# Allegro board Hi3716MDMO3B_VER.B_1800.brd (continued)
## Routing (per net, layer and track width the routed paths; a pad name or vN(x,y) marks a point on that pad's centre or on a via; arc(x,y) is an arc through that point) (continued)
$13N54: length 4
  TOP w0.127: Q8.1 208.82,107.71 209.33,108.21 R126.2 R125.1
$13N57: length 5.1
  TOP w0.127: R125.2 211.24,110.78 J17.2
$14N137: length 1.4
  TOP w0.127: R69.1 D17.1
$15N244: length 2.8
  TOP w0.254: U17.6 229.02,125.24 229.39,125.62 R251.2
$15N245: length 2.8
  TOP w0.254: R250.2 227.36,125.62 227.75,125.23 U17.7
$15N246: length 3.1
  TOP w0.254: R252.2 226.48,125.31 U17.8
$15N325: length 4.5
  TOP w0.254: U12.4 224.21,123.18 223.29,124.1 R65.2
$16N143: length 2
  TOP w0.127: U9.11 208.09,127.26 R5.1
$16N153: length 19.8
  TOP w0.254: R89.1 212.95,123.07 C60.1 211.78,125.96 211.13,126.61 U9.12 208.93,126.61 208.32,125.99 206.16,125.99 204.43,127.72 R113.1 R175.1
$16N171: length 2.1
  TOP w0.127: R49.2 206.67,128.3 206.73,128.24 R190.1 207.17,127.77 207.27,127.67 R5.2
$16N236: length 2
  TOP w0.127: C27.2 215.95,128.56 U9.6
$16N249: length 27.5
  TOP w0.254: R90.2 215.41,122.94 C57.2 215.4,123.48 214.67,124.22 214.67,126.17 215.11,126.61 U9.3 218.59,126.61 219.24,127.26 219.24,129.42 218.35,130.31 216.06,130.31 214.36,132.01 208.01,132.01 207.06,132.96 R112.1 R174.2
$16N268: length 5.1
  TOP w0.254: R92.1 218.96,122.72 219.54,122.13 R88.2 C180.1 216.61,121.55 R90.1
$16N273: length 5.5
  TOP w0.254: C57.1 R92.2 217.49,125.33 216.86,125.96 U9.2
$16N280: length 1.5
  TOP w0.254: R88.1 220.36,120.07 C234.2
$16N296: length 12.6
  TOP w0.127: C38.1 R50.2 208.55,122.19 R185.1 208.55,123.72 v1(208.32,123.96) ; U9.5 v1(214.67,127.91)
  BOTTOM w0.127: v1(208.32,123.96) 212.27,127.91 v1(214.67,127.91)
$16N316: length 3.9
  TOP w0.127: U9.7 213.76,129.21 213.29,129.68 C28.1
$16N318: length 3.6
  TOP w0.127: C28.2 212.48,129.65 212.04,129.21 U9.8
$16N327: length 6.7
  TOP w0.254: U9.13 209.17,125.96 208.82,125.61 208.82,124.85 209.59,124.09 210.48,124.09 210.97,123.6 C60.2 210.97,121.83 R109.1
$16N332: length 3.9
  TOP w0.254: R87.1 R109.2 C181.1 R89.2
$16N368: length 2.1
  TOP w0.254: C235.1 211.01,118.79 211.01,119.77 R87.2
$16N387: length 7.2
  TOP w0.508: U11.2 182.53,141.37 183.64,140.25 C102.1 LB17.2
$17N94: length 5.2
  TOP w0.165: U22.13 249.04,136.36 248.83,136.15 248.83,133.49 248.2,132.86 248.2,132.63 R30.1
$17N123: length 4.4
  TOP w0.508: U13.1 244.59,110.21 244.73,110.35 R8.1 244.86,112.53 R192.1
$17N126: length 3.5
  TOP w0.381: C182.1 243.85,104.38
  TOP w0.635: 240.45,107.05 C39.1 237.91,107.05
$17N128: length 7.8
  TOP w0.381: R192.2 251.62,112.53 253.91,110.25
$17N139: length 3.2
  TOP w0.165: R30.2 248.23,131.03 248.23,130.7 R63.2 248.32,129.67 248.32,129.19 C52.1
$17N140: length 3.3
  TOP w0.165: C55.1 247.81,129.24 247.81,129.64 R63.1 247.94,130.76 247.94,130.96 R31.2
$17N221: length 7.2
  TOP w0.127: R28.1 C50.1 250.89,130.69 249.97,131.61 249.97,135.53 250.09,135.65 U22.14
$17N517: length 2.9
  TOP w0.152: U22.17 251.59,135.93 253.13,134.39 C47.1
$17N528: length 1.3
  TOP w0.152: C1.1 R29.2
$17N535: length 3.2
  TOP w0.152: R29.1 251.05,133.78 C135.1 250.59,135.07 U22.15
$17N549: length 5.5
  TOP w0.165: R31.1 247.91,132.63 247.91,132.98 248.54,133.61 248.54,136.27 248.84,136.58 U22.12
$17N569: length 12.7
  TOP w0.203: U22.8 247.6,139.11 247.05,138.57 247.05,135.9 246.92,135.78 C262.1 246.13,135.57 243.79,135.57 243.23,136.13 243.23,139.97 X2.1
$17N571: length 12.4
  TOP w0.203: X2.2 243.24,133.71 244.22,134.69 C263.1 246.35,134.69 247.43,135.77 247.43,138.06 247.99,138.61 U22.9
$17N582: length 30.7
  TOP w0.127: R35.2 241.11,124.62 R43.1 C33.1 240.96,126.78 240.96,127.77 240.17,128.56 240.17,142.27 241.64,143.75 244.79,143.75 245.78,142.76 245.78,140.98 246.4,140.36 U22.6
$17N583: length 29.9
  TOP w0.127: U22.7 248.84,139.62 246.59,139.62 245.4,140.81 245.4,142.63 244.61,143.42 241.74,143.42 240.45,142.12 240.45,128.79 241.34,127.9 241.34,127.36 C34.1 R41.1 R37.2
$17N610: length 2.8
  TOP w0.152: C61.2 248.14,141.57 249.38,141.57 250.09,140.86 U22.5
$17N615: length 3.7
  TOP w0.152: C143.2 248.68,142 249.44,142 250.59,140.84 U22.4
$17N624: length 3.6
  TOP w0.44: C187.2 248.92,145.17 249.95,144.13 ; C188.1 249.95,144.13 ; 249.95,144.13 D15.3
$17N628: length 1.8
  TOP w0.254: U22.3 251.09,141.36
  TOP w0.44: 251.09,141.36 C188.2
$17N631: length 1.6
  TOP w0.44: C187.1 247.4,146.67 R27.2
$17N637: length 2.8
  TOP w0.152: L3.1 254.67,135.78 253.33,137.11 U22.19
$17N639: length 2.6
  TOP w0.152: L3.2 254.28,137.3 253.47,138.11 U22.21
$17N641: length 4.7
  TOP w0.152: U22.20 253.34,137.61 254.37,136.58 256.04,136.58 L1.1
$17N643: length 4.5
  TOP w0.152: U22.22 252.84,138.61 253.48,138.61 254.04,138.06 255.69,138.06 256.39,137.35 L1.2
$17N657: length 2
  TOP w0.254: U22.24 253.05,139.61 253.15,139.71
  TOP w0.44: 253.15,139.71 253.66,139.71 253.78,139.84 arc(254.05,140.24) L5.2
$17N674: length 1
  TOP w0.44: C48.2 L5.1
$17N676: length 2.2
  TOP w0.44: C190.1 C185.2 257.66,141.11 arc(257.24,140.83) C48.1
$17N678: length 3.8
  TOP w0.44: C189.1 258.53,143.49 arc(259.11,143.37) C184.1 ; C184.1 L12.2 ; C184.1 C206.2
$17N683: length 1.3
  TOP w0.44: 260.12,139.98 L9.2
$17N685: length 1
  TOP w0.44: L10.2 255.71,143.24 C190.2
$17N699: length 4.4
  TOP w0.254: R64.1 255.99,139.51 254.98,139.51 254.65,139.18 C134.2 254.48,139.11 U22.23
$17N726: length 2.1
  TOP w0.44: 259.13,140.97 259.13,140.97 C185.1 C184.2
$17N732: length 1
  TOP w0.44: C189.2 L11.2
$17N744: length 4.6
  TOP w0.254: U22.18 252.09,136.07 252.89,135.26 253,135.26 C41.2 255.55,134.1 R84.1
$17N767: length 1.7
  TOP w0.44: L12.1 262.18,143.04 arc(262.72,142.94) D13.3
$18N11: length 2.6
  TOP w0.127: R32.2 R231.2 261.53,76.58 Q11.2
$18N28: length 7.5
  TOP w0.127: U23.13 248.57,71.63 248.19,71.26 R236.1 246.31,72.5 246.03,72.79 U23.11
$18N32: length 54.1
  TOP w0.127: U23.9 243.49,72.77 243.11,72.4 226.35,72.4 221.04,67.09 208.11,67.09 R36.2
$18N33: length 6.4
  TOP w0.127: R222.2 R9.2 261.76,90.2 262.16,89.8 262.16,88.27 261.91,88.02 260.51,88.02 260.26,87.77 Q2.1
$18N35: length 5.5
  TOP w0.381: R9.1 262.57,87.16 Q2.2
  TOP w0.508: LB20.2 Q2.2
$18N36: length 1.5
  TOP w0.508: R274.1 260.28,89.16 Q2.3
$18N96: length 8
  TOP w0.127: J1.6 254.28,69.5 C307.1 R129.2 R128.1 R106.2
$19N8: length 18.8
  TOP w0.381: R136.1 27.47,73.92 27.98,73.42 30.26,73.42 31.02,74.18 31.02,84.46 30.64,84.85 29.63,84.85 28.97,85.51 C198.1 28.23,85.73
$19N10: length 20
  TOP w0.381: 28.87,107.83 C199.1 29.48,107.48 30.14,106.82 30.14,100.09 29.12,99.07 29.12,95.77 28.74,95.39 28.11,95.39 27.43,96.07 R137.1
  TOP w0.635: C236.1 28.95,115.5 ; C236.1 27.87,114.23 ; C236.1 28.95,112.96
$19N25: length 2.3
  TOP w0.254: D12.2 11.24,103.36 R241.1
$19N26: length 2
  TOP w0.254: R241.2 12.7,101.09 Q9.3
$19N27: length 1.8
  TOP w0.381: Q9.2 R4.1
$19N28: length 1.8
  TOP w0.381: Q9.1 R38.2
$19N31: length 1.5
  TOP w0.254: Q10.1 10.03,80.45 R39.2
$19N32: length 1.9
  TOP w0.381: Q10.2 R3.1
$19N33: length 2.4
  TOP w0.254: R240.2 12.2,83.89 Q10.3
$19N34: length 2.3
  TOP w0.254: D11.2 10.73,87.11 R240.1
$19N40: length 3.2
  TOP w0.508: S2.1 R242.2
$19N44: length 3.4
  TOP w0.381: C63.1 26.29,75.52 C252.1 26.19,76.48 26.03,76.63 U6.6
$19N56: length 2.3
  TOP w0.381: C197.1 28.57,75.76 U6.8
$19N57: length 2.3
  TOP w0.381: R136.2 27.47,76.46 27.3,76.63 U6.7
$19N58: length 1.7
  TOP w0.381: C228.1 30.08,83.18 U6.1
$19N59: length 1
  TOP w0.381: C252.2 25.4,75.6 R238.1
$19N60: length 3.8
  TOP w0.381: R1.1 23.19,75.65 R83.1 24.38,76.17 24.76,76.55 U6.5
$19N61: length 4.5
  TOP w0.381: v1(28.48,84.72) 28.99,84.72 29.58,84.13 C228.2
  BOTTOM w0.381: v1(28.48,84.72) v1(25.94,84.72)
$19N64: length 5
  TOP w0.381: C229.2 29.5,106.56 v1(29.12,106.94)
  BOTTOM w0.381: v1(29.12,106.94) v1(25.18,106.94)
$19N65: length 3.4
  TOP w0.381: R10.1 R82.1 23.62,98.02 24,98.4 U20.5
$19N66: length 1
  TOP w0.381: C253.2 24.61,97.72 24.61,96.76 R239.1
$19N67: length 1.7
  TOP w0.381: U20.1 29.49,105.27 C229.1
$19N68: length 2.7
  TOP w0.381: R137.2 26.54,98.63 U20.7
$19N69: length 2.5
  TOP w0.381: U20.8 27.81,98.74 28.32,98.23 C200.1
$19N80: length 3.4
  TOP w0.381: U20.6 25.27,98.61 25.42,98.46 C253.1 25.53,97.62 C64.1
$20N482: length 7
  TOP w0.127: R44.2 170.22,18.17 D16.1
$20N487: length 2.9
  TOP w0.127: R45.1 168.62,20.08 D18.2
$20N488: length 56.6
  TOP w0.127: v1(58.71,27.19) 58.71,26.2 73.22,11.69 91.86,11.69 92.24,11.31 U8.20
  BOTTOM w0.127: D6.8 67.69,27.19 v1(58.71,27.19)
$20N489: length 55.3
  TOP w0.127: v1(59.3,27.7) 59.3,26.16 73.38,12.07 94.65,12.07 96.05,10.68 U8.23
  BOTTOM w0.127: D6.6 65.92,28.42 65.19,27.7 v1(59.3,27.7)
$20N490: length 50.5
  TOP w0.127: D6.4 59.8,29.46 59.8,26.19 73.54,12.46 95.79,12.46 97.32,10.93 U8.24
$20N491: length 66.1
  TOP w0.127: v1(60.31,28.2) 60.31,26.22 73.69,12.84 98.08,12.84 99.86,11.06 U8.26
  BOTTOM w0.127: D6.12 55.86,30.49 D6.2 57.54,28.71 59.8,28.71 v1(60.31,28.2)
$20N492: length 58.2
  TOP w0.127: U8.27 101.13,11.44 99.35,13.22 73.98,13.22 v1(60.77,26.43)
  BOTTOM w0.127: D6.1 57.28,26.43 v1(60.77,26.43)
$20N493: length 14.6
  TOP w0.127: R140.2 72.68,26.27 D6.7 68.46,35.47 D6.9
$20N494: length 13.7
  TOP w0.127: R127.2 63.05,27.3 61.89,28.46 61.89,32.39 58.84,35.44 58.84,37.47 D6.14
$20N495: length 32.1
  TOP w0.127: v1(72.68,19.19) R140.1 ; v1(68.87,15.38) 72.93,11.31 85.13,11.31 85.89,10.55 U8.15
  BOTTOM w0.127: v1(68.87,15.38) v1(72.68,19.19)
$20N496: length 55.1
  TOP w0.127: R139.1 71.17,19.87 75.03,16.01 84.62,16.01 v1(85.38,16.77) 85.89,17.28 U8.14 ; v1(95.79,16.14) 97.07,14.86 S10.3 S10.4
  BOTTOM w0.127: v1(85.38,16.77) 86.02,16.14 v1(95.79,16.14)
$20N502: length 3.7
  TOP w0.127: R16.1 U8.1
$20N503: length 23.1
  TOP w0.127: D6.16 54.39,36.84 56.3,36.84 56.93,37.47 56.93,38.62 57.5,39.19 59.03,39.19 59.47,38.74 59.47,35.7 62.27,32.9 62.27,28.84 64.4,26.71 R131.2
$20N504: length 66.1
  TOP w0.127: S5.4 S5.3 107.35,27.56 105.07,25.28 95.41,25.28 92.24,22.11 U8.9 92.24,16.84 89.38,13.98 74.36,13.98 64.4,23.94 R131.1
$20N505: length 13.8
  TOP w0.127: R132.2 65.75,26.62 64.55,27.82 64.55,34.3 D6.13
$20N506: length 93.3
  TOP w0.127: S6.4 S6.3 132.62,25.16 122.59,25.16 118.53,29.22 108.11,29.22 104.56,25.66 95.03,25.66 90.97,21.6 U8.10 90.97,16.9 88.43,14.36 74.52,14.36 65.75,23.13 R132.1
$20N507: length 11.1
  TOP w0.127: R133.2 67.11,27.17 65.95,28.33 v1(65.19,28.33)
  BOTTOM w0.127: D6.3 59.09,30.49 61.25,28.33 v1(65.19,28.33)
$20N508: length 77.7
  TOP w0.127: R133.1 67.11,22.31 74.68,14.74 87.54,14.74 89.7,16.9 U8.11 89.7,21.09 94.65,26.04 104.3,26.04 108.11,29.85 118.78,29.85 121.07,27.56 S7.3 S7.4
$20N509: length 7.5
  TOP w0.127: v1(65.19,29.22) 66.71,29.22 68.46,27.47 R134.2
  BOTTOM w0.127: v1(65.19,29.22) 64.65,29.22 D6.5
$20N510: length 48.9
  TOP w0.127: S8.4 S8.3 95.28,27.56 88.43,20.71 U8.12 88.43,17.03 86.52,15.12 74.84,15.12 68.46,21.5 R134.1
$20N511: length 13.3
  TOP w0.127: D6.11 66.97,36.96 66.97,29.73 69.81,26.88 R138.2
$20N512: length 68.9
  TOP w0.127: R138.1 69.81,20.68 74.99,15.5 85.51,15.5 87.16,17.15 U8.13 87.16,20.33 93.76,26.93 93.76,32.9 101.12,40.26 S9.3 S9.4
$20N513: length 26.5
  TOP w0.127: R139.2 67.35,30.1 67.35,38.49 66.2,39.63 57.38,39.63 D6.15
$20N555: length 105.3
  TOP w0.127: S4.4 S4.3 144.17,24.01 95.67,24.01 93.51,21.85 U8.8 93.51,16.65 90.46,13.6 74.2,13.6 63.05,24.76 R127.1
$20N573: length 15.5
  TOP w0.381: D4.3 159.93,14.49 156.75,11.31 C157.1 C73.1 R108.1
$21N8: length 16.6
  TOP w0.178: J29.2 63.26,137.58 63.26,124.33 J18.1
$21N51: length 15.7
  TOP w0.178: J29.3 64.56,138.53 J18.2
$21N65: length 3.7
  TOP w0.127: R197.1 J27.5
$21N352: length 3.7
  TOP w0.127: R47.2 S1.4
$21N355: length 3.7
  TOP w0.127: R48.1 S1.3
$21N358: length 4
  TOP w0.127: J11.1 R48.2

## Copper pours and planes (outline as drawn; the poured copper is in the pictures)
1V2_CTRL on TOP (solid shape): 176.44,109.23 176.82,108.85 177.07,108.85 178.44,107.49 178.44,106.54 178.31,106.41 177.98,106.41 176.94,107.45 161.07,107.45 159.42,107.45 159.42,107.45 152.12,100.15 152.12,93.54 151.67,93.1 148.5,93.1 148.12,93.48 148.12,103.39 149.83,103.39 149.83,105.67 153.45,105.67 153.45,105.93 153.2,105.93 153.2,105.67 152.94,105.67 152.94,105.93 152.69,105.93 152.69,105.67 148.12,105.67 148.12,105.8 148.5,106.18 154.2,106.18 157.26,109.24 175.56,109.24 175.56,109.24 176.44,109.24
1V2_CTRL on TOP (solid shape): 183.84,104.87 183.84,104.48 184,104.32 186.41,104.32 186.7,104.61 186.7,104.95 186.81,105.06 187.95,105.06 189.12,103.9 199.53,103.9 200.36,103.07 200.36,94.47 200.52,94.3 201.31,94.3 201.4,94.21 201.4,93.82 201.29,93.71 200.58,93.71 200.41,93.53 200.41,85.52 200.57,85.35 201.2,85.35 201.33,85.23 201.33,84.72 201.2,84.59 200.57,84.59 200.35,84.37 200.35,83.19 199.71,82.56 197.89,82.56 197.64,82.64 197.4,82.56 195.74,82.56 195.62,82.69 195.62,83.7 195.74,83.83 198.86,83.83 199.07,84.04 199.07,101.48 197.91,102.64 182.39,102.64 182.05,102.31 182.05,85.35 183.04,84.36 183.04,84.34 183.17,84.21 183.81,84.21 184.19,83.83 184.19,81.8 184.12,81.73 183.67,81.73 183.52,81.87 183.52,82.64 182.06,84.09 180.61,84.09 180.39,84.31 180.39,103.91 180.69,104.21 182.34,104.21 182.51,104.38 182.51,104.82 182.76,105.08 183.64,105.08
1V2_CTRL on BOTTOM (solid shape): 177.9,108.33 177.9,108.26 179.05,107.11 179.12,107.11 180.21,106.02 180.21,106.02 180.81,105.42 180.81,105.11 180.81,105.11 180.81,104.9 180.81,104.83 180.81,104.71 180.83,104.7 180.83,104.69 180.93,104.53 181.08,104.43 181.09,104.43 182.27,103.25 182.27,102.23 182.03,101.99 180.12,101.99 178.21,103.89 178.21,104.9 176.42,106.69 176.42,107.43 175.69,108.16 175.69,108.86 175.8,108.98 177.26,108.98
1V2_STANDBY on TOP (solid shape): 153.96,78.11 155.74,78.11 155.87,77.99 155.87,77.48 155.74,77.35 153.96,77.35 153.58,76.97 153.58,76.59 153.33,76.34 151.29,76.34 151.04,76.08 151.04,74.81 150.91,74.69 145.32,74.69 145.2,74.81 145.2,77.35 144.94,77.61 142.78,77.61 142.66,77.73 142.66,79 142.78,79.13 144.94,79.13 145.2,79.38 145.2,80.02 145.45,80.27 151.8,80.27
1V5_DDR3 on TOP (solid shape): outline of 107 points within 137.96,81.7 183.26,107.19
1V5_DDR3 on BOTTOM (solid shape): outline of 219 points within 159.41,84.97 171.62,97.02
3V3 on TOP (solid shape): outline of 103 points within 125.25,79.51 140.75,85.99
3V3_MOS on TOP (solid shape): 198.75,101.39 198.75,84.29 198.55,84.08 197.52,84.08 197.38,84.22 197.38,86.64 197.75,87 197.75,100.48 196.89,101.35 194.73,101.35 194.35,100.97 194.35,99.7 194.09,99.45 192.57,99.45 192.31,99.7 192.31,100.72 192.06,100.97 182.54,100.97 182.39,101.12 182.39,102.26 182.49,102.37 197.78,102.37
3V3_MOS on BOTTOM (solid shape): 198.91,84.85 198.91,83.58 199.42,83.07 200.44,83.07 201.59,81.92 201.59,81.42 201.33,81.16 200.95,81.16 200.06,82.05 198.54,82.05 197.9,82.69 197.51,82.69 197.38,82.81 197.38,82.94 198.03,82.94 198.03,83.19 197.78,83.19 197.78,82.94 197.38,82.94 197.38,83.58 198.03,83.58 198.03,83.83 197.78,83.83 197.78,83.58 197.38,83.58 197.38,84.08 198.03,84.08 198.03,84.34 197.78,84.34 197.78,84.08 197.38,84.08 197.38,84.84 197.52,84.98 198.78,84.98
3V3_PWR on TOP (solid shape): 16.65,88.94 16.65,83.47 17.69,82.43 17.69,81.67 15.98,81.67 15.98,79.38 17.69,79.38 17.69,79.26 19.59,77.35 19.59,74.18 19.85,73.92 20.48,73.92 23.53,70.88 23.53,67.95 23.15,67.57 18.96,67.57 18.58,67.95 18.58,70.24 16.17,72.65 16.17,76.21 13.75,78.62 13.75,88.27 14.64,89.16 16.42,89.16
3V3_T on BOTTOM (solid shape): 251.55,124.88 251.55,123.43 251.47,123.35 250.73,123.35 250.66,123.43 250.66,124.88 250.79,125 251.42,125
3V3_TS on TOP (solid shape): 260.26,97.51 260.33,97.6 260.44,97.57 261.12,97.16 261.87,97.41 261.98,97.42 262.04,97.33 262.04,95.51 261.4,94.88 261.4,93.48 261.78,93.1 261.78,91.58 261.53,91.32 259.12,91.32 258.86,91.58 258.86,93.1 258.35,93.61 258.35,94.88 260.26,96.78
5V0 on TOP (solid shape): 129.96,80.4 129.96,75.57 129.7,75.32 128.43,75.32 128.18,75.57 128.18,80.53 128.31,80.65 129.7,80.65
5V0 on TOP (solid shape): outline of 93 points within 128.18,83.58 138.59,99.83
5V0 on BOTTOM (solid shape): 129.7,85.1 129.7,79.51 129.45,79.26 128.43,79.26 128.18,79.51 128.18,85.1 128.31,85.23 129.58,85.23
5V0_MOS on TOP (solid shape): 142.53,123.07 142.53,121.42 142.4,121.29 139.1,121.29 138.85,121.55 138.85,122.95 139.1,123.2 142.4,123.2
5V0_PWR on TOP (solid shape): 14.37,113.31 14.39,113.27 14.39,110.63 18.32,106.69 18.32,104.07 16.57,104.07 16.57,101.78 18.32,101.78 18.32,95.64 17.82,95.13 15.4,95.13 14.9,95.64 14.9,105.17 10.07,109.99 10.07,113.29 10.45,113.67 14.01,113.67
5V0_PWR on BOTTOM (solid shape): 17.94,97.42 17.94,95.26 17.56,94.88 14.77,94.88 13.24,93.35 13.24,82.05 18.32,76.97 18.32,68.34 17.94,67.95 14.01,67.95 13.63,68.34 13.63,76.46 9.94,80.15 9.94,95.13 12.61,97.8 17.56,97.8
5V0_TS on TOP (solid shape): 233.84,101.61 239.18,101.61 239.53,101.25 239.53,101.06 238.27,101.06 238.27,99.36 237.49,99.36 236.51,100.34 236.25,100.34 236.24,100.35 232.18,100.35 231.43,101.1 231.43,102.37 231.56,102.5 232.95,102.5
5V0_VBUS0 on TOP (solid shape): outline of 160 points within 138.86,124.22 148.49,141.87
5V0_VBUS1 on TOP (solid shape): 157.14,128.15 159.55,128.15 161.72,125.98 161.73,125.97 161.75,125.94 161.75,125.91 161.75,125.88 161.74,125.85 161.72,125.83 161.7,125.81 161.67,125.8 161.65,125.8 159.93,125.8 159.93,124.06 159.57,123.71 158.28,123.71 155.99,121.42 155.14,121.42 155.14,123.35 153.47,123.35 153.45,123.35 153.42,123.36 153.4,123.37 153.38,123.4 153.37,123.43 153.36,123.45 153.37,123.48 153.38,123.51 153.39,123.52 154.98,125.1 154.98,126.25 153.83,127.39 159.04,127.39 159.04,127.77 158.79,127.77 158.79,127.39 158.53,127.39 158.53,127.77 158.28,127.77 158.28,127.39 153.83,127.39 152.82,128.41 152.82,129.8 152.94,129.93 155.36,129.93
12V0_PWR on TOP (solid shape): 30.77,127.9 30.77,127.01 31.28,126.5 32.93,126.5 33.18,126.25 33.18,122.95 34.07,122.06 35.34,122.06 35.72,121.68 35.72,90.41 34.71,89.4 34.71,81.18 34.71,81.18 34.71,74.28 34.71,74.28 34.71,71 31.41,67.7 28.99,67.7 28.74,67.95 28.74,70.26 28.75,70.27 28.75,70.61 28.74,70.63 28.74,71 29.12,71.38 30.39,71.38 31.66,72.65 31.66,87.88 31.67,87.89 31.91,88.53 31.67,89.16 31.66,89.18 31.66,89.42 32.29,90.05 32.29,92.08 33.18,92.97 33.18,119.77 32.8,120.15 31.53,120.15 31.28,120.41 31.28,122.56 31.25,122.59 31.25,122.61 31.25,122.62 31.11,123.03 30.7,123.17 30.68,123.17 30.66,123.18 29.37,124.47 24.17,124.47 23.87,124.76 23.8,124.84 23.79,124.85 23.79,124.87 23.79,128.15 24.17,128.53 30.14,128.53
GND on TOP (solid shape): 252.13,137.12 249.52,137.12 249.52,139.68 252.13,139.68
GND on TOP (solid shape): 129.45,117.23 129.45,114.06 129.32,113.93 126.27,113.93 126.15,114.06 126.15,117.23 126.27,117.36 129.32,117.36
GND on TOP (solid shape): 237.4,102.88 237.4,102.37 237.27,102.24 233.72,102.24 233.34,102.63 233.34,103.51 233.72,103.9 236.38,103.9
GND on TOP (solid shape): 260.77,74.56 260.77,74.3 256.2,69.73 255.94,69.73 255.69,69.99 255.69,71 259.5,74.81 260.51,74.81
GND on TOP (solid shape): 208.68,83.39 208.68,82.07 211.87,78.88 211.87,78.62 211.78,78.53 211.12,78.53 205.27,84.38 205.27,84.85 205.36,84.94 207.13,84.94
GND on TOP (solid shape): 211.45,125.4 211.45,124.55 211.24,124.34 210.69,124.34 210.61,124.42 209.72,124.42 209.16,124.99 209.16,125.43 209.21,125.49 211.36,125.49
GND on TOP (solid shape): 235.24,89.15 235.24,80.53 232.32,77.61 218.35,77.61 217.84,78.11 217.84,89.29 218.21,89.66 234.73,89.66
GND on TOP (solid shape): 143.93,151.01 143.93,143.9 143.93,143.9 143.93,142.95 142.64,141.66 139.51,141.66 139.39,141.79 139.39,150.93 139.79,151.33 143.61,151.33
GND on TOP (solid shape): 120.94,120.53 120.94,120.28 120.81,120.15 120.18,120.15 119.54,119.52 119.53,119.5 119.53,112.01 119.42,111.9 118.7,111.9 118.43,112.17 118.43,120.3 118.78,120.66 120.81,120.66
GND on TOP (solid shape): 223.68,74.81 223.68,73.67 223.3,73.29 217.21,73.29 217.08,73.16 217.08,72.65 216.95,72.53 216.71,72.53 215.94,73.3 215.94,74.69 216.19,74.94 223.56,74.94
GND on TOP (solid shape): 160.69,73.8 160.69,73.54 160.44,73.29 160.06,73.29 158.66,74.69 154.09,74.69 153.96,74.81 153.96,75.32 154.09,75.45 155.99,75.45 156.12,75.57 156.12,76.84 156.25,76.97 157.52,76.97
GND on TOP (solid shape): 143.93,83.07 143.93,81.8 143.67,81.54 142.53,81.54 142.4,81.42 142.4,79.11 142.4,79.11 142.4,77.63 142.4,77.63 142.4,77.1 142.28,76.97 141.68,76.97 141.51,77.14 141.51,83.07 141.77,83.32 143.67,83.32
GND on TOP (solid shape): 167.95,81.59 168.01,81.59 168.06,81.54 168.06,81.29 167.93,81.16 166.47,81.16 165.26,82.37 165.26,82.89 165.26,83.78 165.28,83.81 165.31,83.83 165.71,83.83
GND on TOP (solid shape): 178.47,81.89 178.47,79.89 178.34,79.77 178.22,79.77 176.69,81.29 175.47,81.29 175.44,81.3 175.42,81.34 175.42,81.54 175.47,81.59 175.53,81.59 176.36,82.43 177.93,82.43
GND on TOP (solid shape): 209.08,72.15 209.08,69.73 209.27,69.54 212.05,69.54 213.32,70.81 214.6,70.81 216.44,68.97 216.44,68.59 216.19,68.34 208.82,68.34 205.4,71.76 205.4,72.27 205.52,72.4 208.82,72.4
GND on TOP (solid shape): 236.51,113.17 236.51,112.81 229.89,106.2 229.89,100.32 232.57,97.64 232.57,96.78 232.33,96.54 214.02,96.54 213.78,96.78 213.78,96.96 218.87,102.05 224.58,102.05 224.65,102.12 224.7,102.12 235.88,113.29 236.38,113.29
GND on TOP (solid shape): 258.74,106.05 258.74,104.4 259.12,104.02 261.4,104.02 261.66,103.77 261.66,102.88 261.4,102.63 245.53,102.63 245.27,102.88 245.27,104.3 245.27,104.3 245.27,105.04 245.65,105.42 253.66,105.42 254.54,106.31 258.48,106.31
GND on TOP (solid shape): 214.16,85.99 214.54,85.61 215.3,84.84 215.3,84.46 215.05,84.21 211.11,84.21 210.73,84.59 209.33,84.59 207.68,86.24 207.68,86.75 207.81,86.88 213.27,86.88
GND on TOP (solid shape): 152.91,74.02 158.18,74.02 159.17,73.03 159.17,72.4 158.91,72.15 153.71,72.15 153.58,72.27 153.58,72.91 153.25,73.24 142.58,73.24 142.4,73.42 142.4,73.92 142.52,74.04 152.89,74.04
GND on TOP (solid shape): 109.86,110.59 109.89,110.61 109.93,110.59 111.75,108.77 111.78,108.66 111.68,108.59 110.24,108.59 109.64,109.19 109.64,110.37
GND on TOP (solid shape): 124.88,83.45 124.88,80.91 125.26,80.53 127.42,80.53 127.8,80.15 127.8,78.24 125.77,76.21 123.1,76.21 122.72,76.59 122.72,78.62 122.46,78.88 120.05,78.88 119.8,79.13 119.8,83.45 120.05,83.7 124.62,83.7
GND on TOP (solid shape): 108.06,20.34 108.17,20.36 108.23,20.27 108.23,18.51 105.61,15.9 103.86,15.9 103.76,15.96 103.79,16.07
GND on TOP (solid shape): 140.49,83.45 140.49,78.99 140.12,78.62 140.12,77.23 141.26,76.08 141.26,75.83 141.01,75.57 139.23,75.57 139.13,75.68 139.13,79.24 138.53,79.84 138.53,80.84 137.7,81.67 137.7,82.94 138.34,82.94 138.34,83.32 138.09,83.32 138.09,82.94 137.7,82.94 137.7,83.45 137.83,83.57 140.36,83.57
GND on TOP (solid shape): 146.34,70.35 146.34,69.73 146.16,69.55 133.05,69.55 132.56,70.04 132.56,70.88 132.53,71.08 132.44,71.27 132.44,71.38 132.53,71.43 145.26,71.43
GND on TOP (solid shape): 187.54,111.96 187.54,110.66 187.17,110.3 186.89,110.3 186.86,110.31 186.84,110.35 186.84,111.14 186.8,111.18 181.23,116.75 181.2,116.86 181.3,116.92 182.57,116.92
GND on TOP (solid shape): 154.68,69.99 154.72,69.97 154.73,69.94 154.73,67.59 154.72,67.56 154.7,67.55 154.43,67.42 154.22,67.21 154.21,67.2 154.18,67.19 153.83,67.19 153.45,67.57 153.45,69.86 153.58,69.99
GND on TOP (solid shape): 248.7,85.35 248.7,85.22 247.03,83.55 247.03,80.76 246.92,80.65 246.42,80.65 246.29,80.78 246.29,82.16 245.76,82.7 241.48,82.7 241.47,82.69 240.83,82.69 240.7,82.81 240.7,84.34 240.83,84.46 245.4,84.46 245.53,84.59 245.6,84.65 245.65,84.72 245.78,84.85 245.78,85.35 245.87,85.44 248.61,85.44
GND on TOP (solid shape): 138.16,77.43 138.2,77.41 138.21,77.38 138.21,75.8 138.2,75.77 138.16,75.75 136.76,75.75 136.51,75.5 135.44,75.5 135.32,75.62 135.32,75.94 135.45,76.07 136.8,76.07 137.84,77.11 137.84,77.38 137.86,77.41 137.9,77.43
GND on TOP (solid shape): 212.17,114.04 212.24,113.94 212.24,110.74 211.62,110.12 211.2,110.12 211.11,110.18 211.13,110.29 211.5,110.67 211.5,113.6 211.52,113.63 211.54,113.64 211.83,113.78 212.06,114
GND on TOP (solid shape): 114.59,109.23 114.62,109.12 114.52,109.05 112.86,109.05 110.88,111.03 110.88,111.29 110.91,111.37 110.92,111.44 110.92,111.83 110.95,111.91 111.03,111.94 111.42,111.94 111.49,111.95 111.56,111.97 111.57,111.98 111.85,111.98
GND on TOP (solid shape): 132.32,113.63 132.42,113.57 132.4,113.45 131.74,112.8 129.9,112.8 129.81,112.9 129.81,112.94 129.84,113.02 129.84,113.09 129.84,113.48 129.87,113.56 129.95,113.59 130.34,113.59 130.41,113.6 130.48,113.62 130.49,113.63
GND on TOP (solid shape): 70.25,26.58 70.31,26.67 70.42,26.65 70.74,26.33 70.74,25.03 70.85,25.03 70.89,25.02 70.9,24.98 70.9,20.22 70.84,20.13 70.73,20.15 70.08,20.79 70.08,24.98 70.1,25.02 70.13,25.03 70.25,25.03
GND on TOP (solid shape): 217.16,125.2 217.16,123.58 217.14,123.54 217.1,123.53 216.95,123.53 216.95,123.33 216.94,123.29 216.9,123.28 216.7,123.28 216.66,123.29 216.65,123.33 216.65,123.38 215.78,123.38 215.75,123.39 215.73,123.43 215.73,123.62 215,124.35 215,125.55 215.01,125.59 215.05,125.6 216.75,125.6
GND on TOP (solid shape): 158.24,69.99 158.28,69.97 158.29,69.94 158.29,69.11 156.74,67.56 156.73,67.55 156.44,67.43 156.22,67.21 156.22,67.2 156.19,67.19 155.63,67.19 155.61,67.2 155.6,67.21 155.46,67.37 155.3,67.48 155.28,67.49 155.27,67.51 155.27,69.94 155.28,69.97 155.32,69.99
GND on TOP (solid shape): 197.48,100.4 197.48,93.21 197.49,93.18 197.5,93.15 197.5,87.23 197.01,86.75 197.01,84.34 196.89,84.21 195.49,84.21 195.24,83.96 195.24,82.43 195.11,82.31 193.33,82.31 193.2,82.43 193.2,82.69 193.08,82.81 188.25,82.81 187.23,81.8 184.57,81.8 184.44,81.92 184.44,83.94 183.91,84.46 183.3,84.46 182.3,85.46 182.3,100.47 182.56,100.72 191.93,100.72 192.06,100.59 192.06,99.6 192.46,99.2 194.2,99.2 194.6,99.6 194.6,100.85 194.85,101.09 196.78,101.09
GND on TOP (solid shape): 171.56,68.32 171.6,68.31 171.61,68.27 171.61,67.89 171.6,67.86 171.56,67.84 170.07,67.84 169.95,67.97 168.07,67.97 167.5,67.4 167.47,67.38 167.43,67.39 167.07,67.56 166.67,67.54 166.55,67.58 166.57,67.71 167.18,68.32
GND on TOP (solid shape): 247.78,143.33 247.78,143.15 247.58,142.96 247.58,141.23 247.71,141.11 249.03,141.11 249.13,141 249.13,140.73 249.08,140.67 246.47,140.67 246.15,140.99 246.15,141.18 247.18,141.18 247.18,141.44 246.8,141.44 246.8,141.18 246.15,141.18 246.15,141.79 247.18,141.79 247.18,142 246.8,142 246.8,141.79 246.15,141.79 246.15,142.2 247.13,142.2 247.13,142.43 246.8,142.43 246.8,142.2 246.15,142.2 246.15,142.68 247.13,142.68 247.13,143.04 246.77,143.04 246.77,142.68 246.15,142.68 246.15,143.02 245.25,143.93 245.25,144.18 245.29,144.22 246.89,144.22
GND on TOP (solid shape): 166.39,139.73 166.39,134.26 166.89,133.76 168.44,132.21 169.71,130.95 178.6,130.95 179.36,131.71 185.54,131.71 199.08,118.17 199.08,108.98 197.95,107.86 197.95,107.22 197.85,107.12 197.14,107.12 197.08,107.19 197.08,107.44 197.09,107.46 197.49,107.86 197.55,107.89 197.6,107.93 198.4,108.73 198.42,108.73 198.54,108.85 198.54,117.23 186.6,129.17 174.28,129.17 174.26,129.14 170.45,129.14 165.77,133.82 165.77,139.71 165.9,139.84 166.28,139.84
GND on TOP (solid shape): 152.4,72.09 152.4,71.43 152.45,71.38 152.45,67.45 152.44,67.43 152.43,67.42 152.27,67.28 152.15,67.09 152.14,67.07 152.11,67.07 151.72,67.07 151.69,67.07 151.67,67.09 151.19,67.53 150.55,67.49 150.53,67.48 150.5,67.49 145.84,72.15 145.81,72.21 145.82,72.27 152.23,72.27
GND on TOP (solid shape): 167.04,88.99 169.12,88.99 169.33,88.78 169.33,88.18 169.22,88.07 169.22,88.04 168.95,87.77 168.57,87.77 168.56,87.77 168.38,87.82 168.21,87.77 168.2,87.77 167.77,87.77 167.76,87.77 167.58,87.82 167.41,87.77 167.4,87.77 166.97,87.77 166.96,87.77 166.81,87.82 166.67,87.8 166.64,87.8 166.62,87.81 166.31,88.11 166.31,88.48 166.28,88.51 166.28,88.91 166.41,89.04 166.99,89.04
GND on TOP (solid shape): 161.8,69.99 161.83,69.97 161.85,69.94 161.85,69.74 159.49,67.38 159.45,67.38 159.43,67.39 158.79,67.56 158.22,67.21 158.22,67.2 158.19,67.19 157.63,67.19 157.61,67.2 157.54,67.3 157.46,67.37 157.43,67.44 157.46,67.52 158.82,68.88 158.82,69.94 158.84,69.97 158.88,69.99
GND on TOP (solid shape): 68.73,27.34 68.79,27.44 68.9,27.41 69.43,26.89 69.46,26.79 69.38,26.71 69.38,25.03 69.5,25.03 69.53,25.02 69.55,24.98 69.55,21.03 69.48,20.94 69.37,20.96 68.73,21.61 68.73,24.98 68.74,25.02 68.78,25.03 68.89,25.03 68.89,26.71 68.78,26.71 68.74,26.73 68.73,26.76
GND on TOP (solid shape): 87.99,20.78 88.1,20.8 88.16,20.71 88.16,19.54 88.15,19.51 88.11,19.49 87.93,19.49 87.93,17.36 88.11,17.36 88.15,17.34 88.16,17.31 88.16,17.14 86.41,15.39 86.02,15.39 85.92,15.45 85.94,15.56 87.43,17.04 87.43,17.31 87.44,17.34 87.48,17.36 87.65,17.36 87.65,19.49 87.48,19.49 87.44,19.51 87.43,19.54 87.43,20.22
GND on TOP (solid shape): 89.26,21.16 89.37,21.18 89.43,21.09 89.43,19.54 89.42,19.51 89.38,19.49 89.2,19.49 89.2,17.36 89.38,17.36 89.42,17.34 89.43,17.31 89.43,17.01 87.43,15.01 87.03,15.01 86.94,15.07 86.96,15.18 88.7,16.92 88.7,17.31 88.71,17.34 88.75,17.36 88.92,17.36 88.92,19.49 88.75,19.49 88.71,19.51 88.7,19.54 88.7,20.6
GND on TOP (solid shape): 90.53,21.54 90.64,21.56 90.7,21.47 90.7,19.54 90.69,19.51 90.65,19.49 90.47,19.49 90.47,17.36 90.65,17.36 90.69,17.34 90.7,17.31 90.7,17.01 88.32,14.63 88.05,14.63 87.95,14.69 87.98,14.8 89.97,16.79 89.97,17.31 89.98,17.34 90.02,17.36 90.19,17.36 90.19,19.49 90.02,19.49 89.98,19.51 89.97,19.54 89.97,20.98
GND on TOP (solid shape): 91.8,22.05 91.91,22.07 91.97,21.98 91.97,19.54 91.96,19.51 91.92,19.49 91.74,19.49 91.74,17.36 91.92,17.36 91.96,17.34 91.97,17.31 91.97,16.95 89.27,14.25 88.94,14.25 88.84,14.31 88.87,14.42 91.24,16.79 91.24,17.31 91.25,17.34 91.29,17.36 91.46,17.36 91.46,19.49 91.29,19.49 91.25,19.51 91.24,19.54 91.24,21.49
GND on TOP (solid shape): 172.25,70.24 172.25,70.18 172.23,70.14 172.2,70.13 166.23,70.13 163.49,67.38 163.45,67.38 163.43,67.39 162.55,67.49 162.07,66.73 162.07,66.42 161.2,65.54 160.18,65.54 159.93,65.8 159.93,67.07 162.38,69.52 162.38,69.94 162.4,69.97 162.43,69.99 164.12,69.99 164.2,70.06 164.45,70.06 164.45,70.32 164.88,70.75 171.74,70.75
GND on TOP (solid shape): 244.89,142.5 244.89,140.73 246.67,138.95 246.67,136.41 246.54,136.28 244.56,136.28 244.38,136.46 244.38,136.66 246.29,136.66 246.29,137.04 245.91,137.04 245.91,136.66 244.38,136.66 244.38,142.53 244.26,142.65 243.98,142.65 243.98,142.66 242.53,142.66 242.53,142.65 242.22,142.65 242.1,142.53 242.1,127.77 242.23,127.64 242.35,127.64 242.35,127.62 244.26,127.62 244.38,127.75 244.38,133.49 246.16,133.49 246.16,133.74 245.91,133.74 245.91,133.49 244.38,133.49 244.38,133.74 244.77,134.12 246.54,134.12 246.67,133.99 246.67,133.81 245.59,132.73 245.59,127.58 245.15,127.14 242.24,127.14 242.23,127.14 242.09,127.14 241.72,127.52 241.72,127.97 241.31,128.38 241.31,142.53 241.87,143.1 244.3,143.1
GND on TOP (solid shape): 68.96,29.6 68.99,29.58 72.25,26.32 72.25,24.95 72.36,24.95 72.4,24.94 72.41,24.9 72.41,19.55 72.41,19.53 72.4,19.51 72.33,19.43 72.28,19.34 72.2,19.28 72.11,19.3 71.44,19.98 71.44,24.98 71.45,25.02 71.49,25.03 71.6,25.03 71.6,26.71 71.11,26.71 68.52,29.31 68.49,29.42 68.58,29.48 68.76,29.52 68.93,29.59
GND on TOP (solid shape): 75.72,97.68 75.72,89.69 77.11,88.29 77.11,85.46 77.11,85.44 77.09,85.42 76.96,85.2 76.98,84.93 76.99,84.91 76.97,84.87 76.94,84.86 76.86,84.86 69.36,92.36 69.36,97.61 69.41,97.7 69.52,97.7 69.81,97.62 70.08,97.77 70.1,97.78 70.12,97.79 72.72,97.79 73.53,98.59 74.81,98.59
GND on TOP (solid shape): 82.8,81.35 82.81,81.32 82.81,81.29 82.71,80.75 82.93,80.24 82.95,80.23 82.95,80.21 82.93,80.17 82.9,80.16 82.82,80.16 82.19,80.79 80.68,80.79 80.65,80.81 80.63,80.85 80.63,80.96 80.25,80.96 80.14,81.06 80.12,81.18 80.21,81.24 80.63,81.24 80.63,81.35 80.65,81.39 80.68,81.4 82.74,81.4
GND on TOP (solid shape): 134.33,75.14 134.33,74.63 134.83,74.63 135.29,74.18 138.16,74.18 138.2,74.16 138.21,74.13 138.21,73.15 138.84,72.52 138.86,72.41 138.77,72.35 129.26,72.35 128.69,72.92 128.69,73.06 128.7,73.09 128.74,73.11 129.88,73.11 129.88,73.48 129.9,73.51 129.93,73.53 130.11,73.53 130.15,73.51 130.16,73.48 130.16,73.36 131.02,73.36 131.02,73.45 131.04,73.49 131.08,73.5 132.58,73.5 132.89,73.81 132.89,75.46 133.01,75.57 133.89,75.57
GND on TOP (solid shape): 114.81,113.74 114.9,113.77 114.97,113.72 115.02,113.66 115.07,113.6 115.08,113.59 115.09,113.56 115.09,110.77 116.18,109.67 116.19,109.65 116.19,109.56 116.21,109.48 116.2,109.39 116.11,109.35 115.23,109.35 112.07,112.51 111.77,112.51 111.74,112.53 111.72,112.56 111.72,113.35 111.85,113.48 112.57,113.48 112.72,113.63 113.44,113.63 113.52,113.61 113.59,113.6 114.48,113.6 114.65,113.64 114.8,113.73
GND on TOP (solid shape): 66.84,27.06 66.84,26.76 66.82,26.73 66.79,26.71 66.67,26.71 66.67,25.03 66.79,25.03 66.82,25.02 66.84,24.98 66.84,22.66 66.78,22.57 66.67,22.59 66.02,23.24 66.02,24.98 66.04,25.02 66.07,25.03 66.19,25.03 66.19,26.71 66.04,26.71 64.82,27.93 64.82,27.97 64.83,28 64.87,28.02 64.89,28.02 64.9,28 65.22,27.9 65.51,28.05 65.52,28.05 65.54,28.06 65.84,28.06
GND on TOP (solid shape): 117.67,21.71 117.77,21.65 117.74,21.54 116.82,20.62 116.79,20.6 116.76,20.61 115.59,20.65 114.8,19.79 114.78,19.77 114.75,19.76 111.07,19.76 111.04,19.77 111.02,19.81 111.02,20.76 108.72,20.76 108.63,20.82 108.65,20.93 109.43,21.71
GND on TOP (solid shape): 62.83,99.51 62.94,99.54 63,99.45 63.04,99.29 63.11,99.14 63.13,99.1 59.08,95.06 59.08,83.52 59,83.42 58.89,83.47 58.08,83.93 57.26,83.48 57.15,83.43 57.07,83.53 57.07,93.75
GND on TOP (solid shape): 82.81,85.59 82.91,85.54 82.9,85.43 82.71,84.84 82.92,84.26 82.93,84.15 82.84,84.1 80.68,84.1 80.65,84.11 80.63,84.15 80.63,84.39 80.5,84.39 80.47,84.42 80.47,84.42 80.39,84.49 80.37,84.6 80.47,84.67 80.63,84.67 80.63,84.78 80.65,84.82 80.68,84.83 81.94,84.83 82.7,85.59
GND on TOP (solid shape): 98.11,22.5 98.14,22.49 98.16,22.45 98.16,21.65 98.27,21.65 98.31,21.63 98.32,21.6 98.32,19.54 98.31,19.51 98.27,19.49 98.09,19.49 98.09,17.36 98.27,17.36 98.31,17.34 98.32,17.31 98.32,16.79 99.04,16.07 99.06,15.96 98.97,15.9 98.24,15.9 97.71,16.43 97.71,17.31 97.73,17.34 97.76,17.36 97.81,17.36 97.81,19.49 97.76,19.49 97.73,19.51 97.71,19.54 97.71,21.65 97.74,21.67 97.75,21.67 97.75,22.45 97.77,22.49 97.8,22.5
GND on TOP (solid shape): 151.97,44.3 152.03,44.4 152.14,44.37 158.27,38.25 158.27,33.7 158.2,33.6 158.09,33.62 151.97,39.75 151.96,39.77 151.97,39.84 151.97,39.9 151.97,40.51 151.82,40.99 151.41,41.31 151.4,41.34 151.4,42.83 151.42,42.85 151.43,42.86 151.82,43.17 151.97,43.64 151.97,44.25
GND on TOP (solid shape): 68.19,27.36 68.19,26.76 68.18,26.73 68.14,26.71 68.03,26.71 68.03,25.03 68.14,25.03 68.18,25.02 68.19,24.98 68.19,21.85 68.13,21.75 68.02,21.78 67.37,22.42 67.37,24.98 67.39,25.02 67.43,25.03 67.54,25.03 67.54,26.71 67.43,26.71 67.39,26.73 67.37,26.76 67.37,27.28 66.06,28.6 65.55,28.6 65.53,28.6 65.51,28.61 65.47,28.66 65.43,28.69 65.38,28.77 65.43,28.86 65.47,28.89 65.51,28.93 65.53,28.95 65.55,28.95 66.6,28.95
GND on TOP (solid shape): 82.71,82.59 82.74,82.58 82.76,82.56 82.99,82.19 83.36,81.96 83.43,81.86 83.36,81.76 83.29,81.74 83.22,81.71 83.19,81.71 82.96,81.94 80.68,81.94 80.65,81.95 80.63,81.99 80.63,82.1 80.52,82.1 80.48,82.12 80.47,82.15 80.47,82.16 80.42,82.21 80.4,82.32 80.49,82.38 80.63,82.38 80.63,82.5 80.65,82.53 80.68,82.55 80.92,82.55 80.97,82.59
GND on TOP (solid shape): 67.39,98.98 67.47,98.95 68.22,98.2 68.22,92.47 68.16,92.37 68.05,92.39 65.96,94.48 65.96,97.69 65.97,97.71 65.98,97.73 66.13,98.09 65.92,98.42 65.87,98.5 65.9,98.58 66.02,98.7 66.05,98.71 66.08,98.71 66.74,98.61 67.32,98.94
GND on TOP (solid shape): 99.38,22.5 99.41,22.49 99.43,22.45 99.43,21.65 99.54,21.65 99.58,21.63 99.59,21.6 99.59,19.54 99.58,19.51 99.54,19.49 99.36,19.49 99.36,17.36 99.54,17.36 99.58,17.34 99.59,17.31 99.59,17.04 100.21,16.42 100.24,16.31 100.14,16.25 99.62,16.25 98.86,17.01 98.86,17.31 98.87,17.34 98.91,17.36 99.08,17.36 99.08,19.49 98.91,19.49 98.87,19.51 98.86,19.54 98.86,21.6 98.87,21.63 98.91,21.65 99.02,21.65 99.02,22.45 99.04,22.49 99.07,22.5
GND on TOP (solid shape): 100.65,22.5 100.68,22.49 100.7,22.45 100.7,21.65 100.81,21.65 100.85,21.63 100.86,21.6 100.86,19.54 100.85,19.51 100.81,19.49 100.63,19.49 100.63,17.36 100.81,17.36 100.85,17.34 100.86,17.31 100.86,17.17 101.23,16.8 101.25,16.69 101.16,16.63 100.76,16.63 100.13,17.26 100.13,17.31 100.14,17.34 100.18,17.36 100.35,17.36 100.35,19.49 100.18,19.49 100.14,19.51 100.13,19.54 100.13,21.6 100.14,21.63 100.18,21.65 100.29,21.65 100.29,22.45 100.31,22.49 100.34,22.5
GND on TOP (solid shape): 64.22,29.81 64.29,29.72 64.29,27.71 65.32,26.68 65.32,25.03 65.44,25.03 65.47,25.02 65.49,24.98 65.49,23.48 65.42,23.38 65.31,23.41 64.67,24.05 64.67,24.98 64.68,25.02 64.72,25.03 64.83,25.03 64.83,26.71 64.72,26.71 64.68,26.73 64.67,26.76 64.67,26.82 62.53,28.95 62.53,29.66 62.59,29.75 62.7,29.73 63.42,29.48 64.11,29.79
GND on TOP (solid shape): 116.88,114.94 116.88,111.64 117.69,110.83 117.69,109.91 117.73,109.69 117.83,109.49 117.84,109.45 117.83,109.42 117.76,109.35 117.13,109.35 117.05,109.39 117.03,109.48 116.96,109.88 116.59,110.04 116.57,110.04 116.55,110.06 115.62,110.99 115.62,113.56 115.62,113.59 115.64,113.6 115.78,113.98 115.56,114.31 115.51,114.38 115.54,114.47 116.27,115.2 116.62,115.2
GND on TOP (solid shape): 59.74,37.5 59.82,37.6 59.93,37.55 60.53,37.04 61.31,37.11 61.34,37.12 61.37,37.1 64.29,34.19 64.29,31.27 64.22,31.17 64.11,31.2 63.42,31.51 62.7,31.25 62.59,31.24 62.53,31.33 62.53,33.01 59.74,35.81
GND on TOP (solid shape): 175.04,144.03 175.04,138.57 174.53,138.06 174.15,138.06 174.15,138.06 171.67,138.06 171.64,138.07 171.63,138.08 171.62,138.11 171.62,138.44 173.77,138.44 173.77,138.69 173.52,138.69 173.52,138.44 173.26,138.44 173.26,138.69 173.01,138.69 173.01,138.44 172.5,138.44 172.5,138.69 172.25,138.69 172.25,138.44 171.99,138.44 171.99,138.69 171.74,138.69 171.74,138.44 171.62,138.44 171.62,139.44 171.08,139.98 169.94,139.98 169.42,140.49 169.42,141.27 169.62,141.47 170.91,141.47 170.93,141.43 170.98,141.35 171.02,141.27 171.08,141.2 171.14,141.14 171.21,141.08 171.28,141.03 171.36,140.98 171.44,140.94 171.52,140.91 171.61,140.89 171.7,140.87 171.79,140.86 171.88,140.86 171.97,140.87 172.05,140.88 172.14,140.91 172.22,140.94 172.31,140.97 172.38,141.02 172.46,141.07 172.53,141.12 172.59,141.19 172.65,141.26 172.7,141.33 172.74,141.41 172.78,141.49 172.81,141.57 172.84,141.66 172.85,141.74 172.86,141.83 172.86,141.88 172.86,143.66 173.61,144.41 174.66,144.41
GND on TOP (solid shape): outline of 88 points within 110.15,121.55 114.95,125.36
GND on TOP (solid shape): outline of 91 points within 247.94,78.62 257.85,88.53
GND on TOP (solid shape): outline of 92 points within 130.34,83.45 139.48,92.59
GND on TOP (solid shape): 110.69,116.77 110.79,116.73 110.9,116.71 110.97,116.71 111.01,116.7 111.02,116.66 111.02,116.12 111.01,116.09 110.98,116.07 110.75,115.91 110.72,115.64 110.73,115.63 110.73,115.59 110.71,115.57 110.71,112.41 110.73,112.39 110.73,112.35 110.71,112.3 110.71,112.25 110.68,112.18 110.61,112.15 110.56,112.15 110.51,112.13 110.47,112.13 110.45,112.15 107.29,112.15 107.27,112.13 107.23,112.13 107.17,112.15 107.12,112.15 107.05,112.18 107.02,112.25 107.02,112.3 107.01,112.35 107.01,112.39 107.02,112.41 107.02,115.57 107.01,115.59 107.01,115.63 107.02,115.69 107.02,115.74 107.05,115.81 107.12,115.84 107.17,115.84 107.23,115.85 107.27,115.85 107.29,115.83 110.45,115.83 110.45,116.7 110.53,116.78 110.68,116.78
GND on TOP (solid shape): 157.14,87.77 157.14,87.16 156.33,86.36 156.33,81.59 163.67,74.24 163.87,74.24 163.87,73.85 162.05,73.85 157.83,78.06 156.17,78.06 152.99,81.24 152.96,81.32 153,81.39 153.28,82.35 152.46,82.93 151.9,82.93 151.14,82.47 151.2,81.47 151.11,81.42 149.13,81.42 149.01,81.54 149.01,82.94 149.13,83.07 154.34,83.07 154.85,83.58 154.85,83.98 154.85,83.98 154.85,85.78 154.88,85.81 154.88,86.67 154.85,86.7 154.85,87.77 154.98,87.89 157.01,87.89
GND on TOP (solid shape): 96.92,21.47 96.92,19.54 96.92,19.51 96.9,19.5 96.82,19.49 96.82,17.36 96.9,17.35 96.92,17.33 96.92,17.31 96.92,16.1 97.72,15.3 97.73,15.29 97.75,15.27 97.75,15.24 97.75,15.21 97.74,15.18 97.72,15.16 97.69,15.14 97.67,15.13 97.65,15.13 97.18,15.13 96.24,16.07 96.23,16.14 96.22,16.2 96.21,16.26 96.19,16.31 96.16,16.36 96.13,16.41 96.09,16.45 96.04,16.49 95.99,16.52 95.94,16.55 95.88,16.56 95.82,16.57 95.76,16.57 95.71,16.56 95.65,16.55 95.6,16.52 95.54,16.49 95.5,16.45 95.46,16.41 95.42,16.36 95.4,16.31 95.38,16.25 95.37,16.2 95.36,16.14 95.36,16.07 95.35,16.04 95.33,16.02 95.3,16.01 95.28,16 95.25,16 95.22,16.01 95.17,16.05 95.17,17.31 95.18,17.33 95.19,17.35 96.54,17.36 96.54,19.49 95.55,19.49 95.55,17.36 95.27,17.36 95.27,19.49 95.19,19.5 95.18,19.51 95.17,19.54 95.17,20.48 95.2,20.51 95.21,20.52 95.24,20.54 95.58,20.54 96.06,21.03 96.06,21.47 96.19,21.6 96.8,21.6
GND on TOP (solid shape): outline of 95 points within 131.75,120.4 137.31,127.01
GND on TOP (solid shape): outline of 96 points within 247.94,71.13 257.85,81.54
GND on TOP (solid shape): 61.56,29.7 61.62,29.6 61.62,28.35 62.78,27.19 62.78,26.76 62.76,26.73 62.73,26.71 62.61,26.71 62.61,25.21 62.55,25.11 62.44,25.13 61.22,26.36 61.2,26.37 61.2,26.4 61.06,26.75 60.7,26.85 60.61,26.87 60.58,26.95 60.58,27.85 60.59,27.87 60.6,27.88 60.69,28.41 60.2,28.62 60.11,28.64 60.07,28.72 60.07,29.35 60.31,29.58 60.33,29.6 60.36,29.59 60.92,29.48 61.45,29.69
GND on TOP (solid shape): 65.71,100.45 65.81,100.39 65.79,100.28 65.54,99.73 65.65,99.14 65.67,99.1 61.49,94.93 61.49,83.69 61.43,83.59 61.31,83.62 60.52,83.93 59.8,83.48 59.69,83.43 59.61,83.53 59.61,94.83 63.5,98.73 64.8,98.97 64.76,100.29 64.75,100.4 64.84,100.45
GND on TOP (solid shape): outline of 104 points within 146.84,7.9 156.68,10.92
GND on TOP (solid shape): outline of 104 points within 78.41,75.26 83.43,80.26
GND on TOP (solid shape): outline of 136 points within 234.61,108.09 254.93,132.72
GND on TOP (solid shape): outline of 159 points within 119.92,94.24 154.47,108.34
GND on TOP (solid shape): outline of 195 points within 147.69,11.71 160.68,29.18
GND on TOP (solid shape): 150.41,44.95 150.5,44.9 150.49,44.79 150.34,44.54 150.29,44.25 150.29,43.64 150.44,43.17 150.83,42.86 150.85,42.85 150.87,42.83 150.87,41.33 150.85,41.3 150.83,41.29 150.44,40.99 150.29,40.51 150.29,39.9 150.77,39.15 151.65,39.24 151.67,39.26 151.71,39.25 157.76,33.2 157.76,29.33 157.69,29.24 157.58,29.26 155.48,31.37 155.46,31.4 155.47,31.43 154.76,33.35 152.9,32.49 152.89,32.48 152.86,32.46 149.17,32.46 149.14,32.47 149.12,32.51 149.12,33.46 148.17,33.46 148.13,33.48 148.12,33.51 148.12,33.75 149.53,35.16 149.53,39.13 149.53,39.16 149.86,39.48 149.97,39.9 149.97,40.51 149.86,40.93 149.53,41.26 149.53,41.28 149.53,42.89 149.54,42.91 149.55,42.92 149.86,43.22 149.97,43.64 149.97,44.25 149.92,44.54 149.78,44.79 149.76,44.9 149.86,44.95
GND on TOP (solid shape): outline of 228 points within 59.37,30.9 66.7,39.37
GND on TOP (solid shape): outline of 249 points within 39.97,143.15 47.97,151.15
GND on TOP (solid shape): outline of 249 points within 39.97,113.59 47.97,121.59
GND on TOP (solid shape): outline of 249 points within 81.88,143.15 89.88,151.15
GND on TOP (solid shape): outline of 249 points within 81.88,113.59 89.88,121.59
GND on TOP (solid shape): outline of 250 points within 39.92,99.97 47.93,107.97
GND on TOP (solid shape): outline of 250 points within 39.92,63.1 47.93,71.1
GND on TOP (solid shape): outline of 250 points within 81.5,99.97 89.5,107.97
GND on TOP (solid shape): outline of 250 points within 81.5,63.1 89.5,71.1
GND on TOP (solid shape): outline of 250 points within 93.16,101.76 101.16,109.76
GND on TOP (solid shape): outline of 250 points within 93.95,63.19 101.95,71.19
GND on TOP (solid shape): outline of 250 points within 188.62,0.93 196.63,8.93
GND on TOP (solid shape): outline of 250 points within 189.26,51.09 197.26,59.09
GND on TOP (solid shape): outline of 250 points within 259.02,110.4 267.02,118.4
GND on TOP (solid shape): outline of 250 points within 259.02,63.41 267.02,71.41
GND on TOP (solid shape): outline of 250 points within 259.11,51.09 267.11,59.09
GND on TOP (solid shape): outline of 250 points within 259.11,0.93 267.11,8.93
GND on TOP (solid shape): outline of 193 points within 209.33,111.64 218.35,130.25
GND on TOP (solid shape): outline of 305 points within 146.76,19.33 172.01,45.97
GND on TOP (solid shape): outline of 283 points within 175.68,65.52 204,79.64
GND on TOP (solid shape): outline of 363 points within 174.53,134.63 190.92,144.72
GND on TOP (solid shape): outline of 384 points within 141.88,131.2 159.93,151.33
GND on TOP (solid shape): outline of 417 points within 135.05,107.71 189.11,132.29
GND on TOP (solid shape): outline of 505 points within 93.25,62.56 195.44,125.36
GND on TOP (solid shape): outline of 1298 points within 48.31,69.86 79.78,102.99
GND on TOP (solid shape): outline of 1424 points within 193.08,109.36 235.4,142.57
GND on TOP (solid shape): outline of 1791 points within 39.74,111.72 89.92,151.41
GND on TOP (solid shape): outline of 2120 points within 172.88,62.49 267.63,151.52
GND on TOP (solid shape): outline of 2224 points within 40,63.18 89.69,108.05
GND on TOP (solid shape): outline of 2516 points within 188.63,0.73 267.3,59.45
GND on TOP (solid shape): outline of 5161 points within 22.01,1.03 184.69,48.4
GND on BOTTOM (solid shape): 84.36,98.16 82.96,98.16 82.96,102.35 84.36,102.35
GND on BOTTOM (solid shape): 84.36,69.37 82.96,69.37 82.96,73.56 84.36,73.56
GND on BOTTOM (solid shape): 86.36,98.16 84.96,98.16 84.96,102.35 86.36,102.35
GND on BOTTOM (solid shape): 86.36,69.37 84.96,69.37 84.96,73.56 86.36,73.56
GND on BOTTOM (solid shape): 237.92,99.41 233.73,99.41 233.73,100.81 237.92,100.81
GND on BOTTOM (solid shape): 237.92,97.41 233.73,97.41 233.73,98.81 237.92,98.81
GND on BOTTOM (solid shape): 266.72,99.41 262.53,99.41 262.53,100.81 266.72,100.81
GND on BOTTOM (solid shape): 266.72,97.41 262.53,97.41 262.53,98.81 266.72,98.81
GND on BOTTOM (solid shape): outline of 249 points within 39.97,143.15 47.97,151.15
GND on BOTTOM (solid shape): outline of 249 points within 39.97,113.59 47.97,121.59
GND on BOTTOM (solid shape): outline of 249 points within 81.88,143.15 89.88,151.15
GND on BOTTOM (solid shape): outline of 249 points within 81.88,113.59 89.88,121.59
GND on BOTTOM (solid shape): outline of 250 points within 39.92,99.97 47.93,107.97
GND on BOTTOM (solid shape): outline of 250 points within 39.92,63.1 47.93,71.1
GND on BOTTOM (solid shape): outline of 250 points within 81.5,99.97 89.5,107.97
GND on BOTTOM (solid shape): outline of 250 points within 81.5,63.1 89.5,71.1
GND on BOTTOM (solid shape): outline of 250 points within 93.16,101.76 101.16,109.76
GND on BOTTOM (solid shape): outline of 250 points within 93.95,63.19 101.95,71.19
GND on BOTTOM (solid shape): outline of 250 points within 188.62,0.93 196.63,8.93
GND on BOTTOM (solid shape): outline of 250 points within 189.26,51.09 197.26,59.09
GND on BOTTOM (solid shape): outline of 250 points within 259.02,110.4 267.02,118.4
GND on BOTTOM (solid shape): outline of 250 points within 259.02,63.41 267.02,71.41
GND on BOTTOM (solid shape): outline of 250 points within 259.11,51.09 267.11,59.09
GND on BOTTOM (solid shape): outline of 250 points within 259.11,0.93 267.11,8.93
GND on BOTTOM (solid shape): outline of 1814 points within 39.68,111.72 90.02,151.41
GND on BOTTOM (solid shape): outline of 3101 points within 188.63,0.73 267.31,59.41
GND on BOTTOM (solid shape): outline of 4375 points within 39.74,62.78 90.09,108.48
GND on BOTTOM (solid shape): outline of 6650 points within 22.01,1.03 184.69,48.4
GND on BOTTOM (solid shape): outline of 15465 points within 93.13,62.62 267.61,151.48
Net_94 on BOTTOM (solid shape): outline of 249 points within 175.68,39.91 183.68,47.91
Net_95 on TOP (solid shape): outline of 249 points within 175.68,39.91 183.68,47.91
Net_96 on BOTTOM (solid shape): outline of 249 points within 22.14,39.91 30.13,47.91
Net_97 on TOP (solid shape): outline of 249 points within 22.14,39.91 30.13,47.91
Net_98 on BOTTOM (solid shape): outline of 249 points within 175.68,1.05 183.68,9.05
Net_99 on TOP (solid shape): outline of 249 points within 175.68,1.05 183.68,9.05
Net_100 on BOTTOM (solid shape): outline of 249 points within 22.14,1.05 30.13,9.05
Net_101 on TOP (solid shape): outline of 249 points within 22.14,1.05 30.13,9.05
Net_448 on BOTTOM (solid shape): 124.84,144.7 122.18,144.7 122.18,145.97 124.84,145.97
Net_449 on BOTTOM (solid shape): 136.4,144.7 133.73,144.7 133.73,145.97 136.4,145.97
Net_450 on BOTTOM (solid shape): 125.86,142.92 123.19,142.92 123.19,144.19 125.86,144.19
Net_451 on BOTTOM (solid shape): 137.42,142.92 134.75,142.92 134.75,144.19 137.42,144.19
Net_452 on BOTTOM (solid shape): 99.7,144.7 97.03,144.7 97.03,145.97 99.7,145.97
Net_453 on BOTTOM (solid shape): 111.25,144.7 108.59,144.7 108.59,145.97 111.25,145.97
Net_454 on BOTTOM (solid shape): 100.71,142.92 98.05,142.92 98.05,144.19 100.71,144.19
Net_455 on BOTTOM (solid shape): 112.27,142.92 109.6,142.92 109.6,144.19 112.27,144.19
P_GND on TOP (solid shape): outline of 145 points within 15.53,90.05 32.93,115.79
P_GND on TOP (solid shape): outline of 139 points within 16.9,73.92 30.63,85.1
P_GND on TOP (solid shape): outline of 155 points within 18.57,95.96 29.74,107.85
P_GND on TOP (solid shape): outline of 249 points within 8.36,54.43 16.36,62.43
P_GND on TOP (solid shape): outline of 249 points within 8.44,142.36 16.44,150.36
P_GND on TOP (solid shape): outline of 249 points within 28.17,54.43 36.17,62.43
P_GND on TOP (solid shape): outline of 665 points within 7.78,52.71 36.49,151.34
P_GND on BOTTOM (solid shape): outline of 249 points within 8.36,54.43 16.36,62.43
P_GND on BOTTOM (solid shape): outline of 249 points within 8.44,142.36 16.44,150.36
P_GND on BOTTOM (solid shape): outline of 249 points within 28.17,54.43 36.17,62.43
P_GND on BOTTOM (solid shape): outline of 1900 points within 7.78,52.84 36.49,151.34
$4N10 on TOP (solid shape): 146.21,99.83 146.21,93.23 145.96,92.97 139.36,92.97 139.1,93.23 139.1,99.7 139.23,99.83 139.74,99.83 139.86,99.7 139.86,97.55 140.5,96.91 142.66,96.91 143.42,97.67 143.42,99.96 143.67,100.21 145.83,100.21
